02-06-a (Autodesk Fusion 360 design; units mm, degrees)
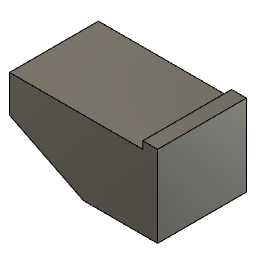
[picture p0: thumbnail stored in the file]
sketch "スケッチ1" plane through (0, 0, 0) normal (0, 0, 1) x axis (1, 0, 0)
  line L1 (-50, 25) -> (50, 25)
  line L2 (-50, -25) -> (-50, 25)
  line L3 (50, -25) -> (-50, -25)
  line L4 (50, 25) -> (50, -25)
  line L5 (-50, -25) -> (50, 25)
  line L6 (50, -25) -> (-50, 25)
  point P6 (0, 0)
  point P1 (0, 0)
  point P2 (50, 25)
  point P3 (-50, 25)
  point P5 (50, -25)
  horizontal L1
  perpendicular L1 L2
  parallel L1 L3
  parallel L2 L4
  coincident L5 P6
  coincident L6 P6
  coincident P1 P6
  dimension "d1" distance P2 P3 = 100
  dimension "d2" distance P2 P5 = 50
extrude "押し出し1" new body sketch "スケッチ1" profile of L1 L2 L3 L4 distance 60
sketch "スケッチ2" plane through (0, 25, 0) normal (0, 1, 0) x axis (-1, 0, 0)
  line L1 (50, 30) -> (50, -30)
  line L2 (-50, 30) -> (50, 30)
  line L3 (-50, -30) -> (-50, 30)
  line L4 (50, -30) -> (-50, -30)
  line L5 (-50, -30) -> (-40, -30)
  line L6 (-50, 30) -> (-50, -30)
  line L7 (-40, 30) -> (-50, 30)
  line L8 (-40, -30) -> (-40, 30)
  point P5 (-50, -30)
  point P7 (-50, -30)
  point P4 (-50, 30)
  point P8 (-50, 30)
  point P6 (-40, -30)
  horizontal L5
  vertical L6
  horizontal L7
  vertical L8
  coincident P5 P7
  coincident P4 P8
  dimension "d5" distance P6 P7 = 10
extrude "押し出し2" add sketch "スケッチ2" profile of L2 L3 L4 L5 L6 L7 L8 along normal blind 5
sketch "スケッチ4" plane through (0, 0, 30) normal (0, 0, 1) x axis (1, 0, 0)
  line L1 (50, 30) -> (50, -25)
  line L2 (40, 30) -> (50, 30)
  line L3 (40, 25) -> (40, 30)
  line L4 (-50, 25) -> (40, 25)
  line L5 (-50, -25) -> (-50, 25)
  line L6 (50, -25) -> (-50, -25)
  line L7 (0, -25) -> (-50, -25)
  line L8 (-50, 0) -> (0, -25)
  line L9 (-50, -25) -> (-50, 0)
  point P8 (-50, -25)
  point P10 (-50, 0)
  point P9 (0, -25)
  parallel L5 L9
  collinear L5 L9
  collinear L6 L7
  dimension "d10" distance P8 P10 = 25
  dimension "d11" distance P8 P9 = 50
extrude "押し出し3" cut sketch "スケッチ4" profile of L5 L6 L7 L8 L9 no distance stored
